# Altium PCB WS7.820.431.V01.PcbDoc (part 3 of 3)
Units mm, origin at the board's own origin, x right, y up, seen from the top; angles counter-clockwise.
Board outline 461 x 63.5 mm, 4 copper layers (Top Layer, Mid-Layer1, Mid-Layer 2, Bottom Layer); 379 components, 227 nets, 1092 pads, 3835 vias.
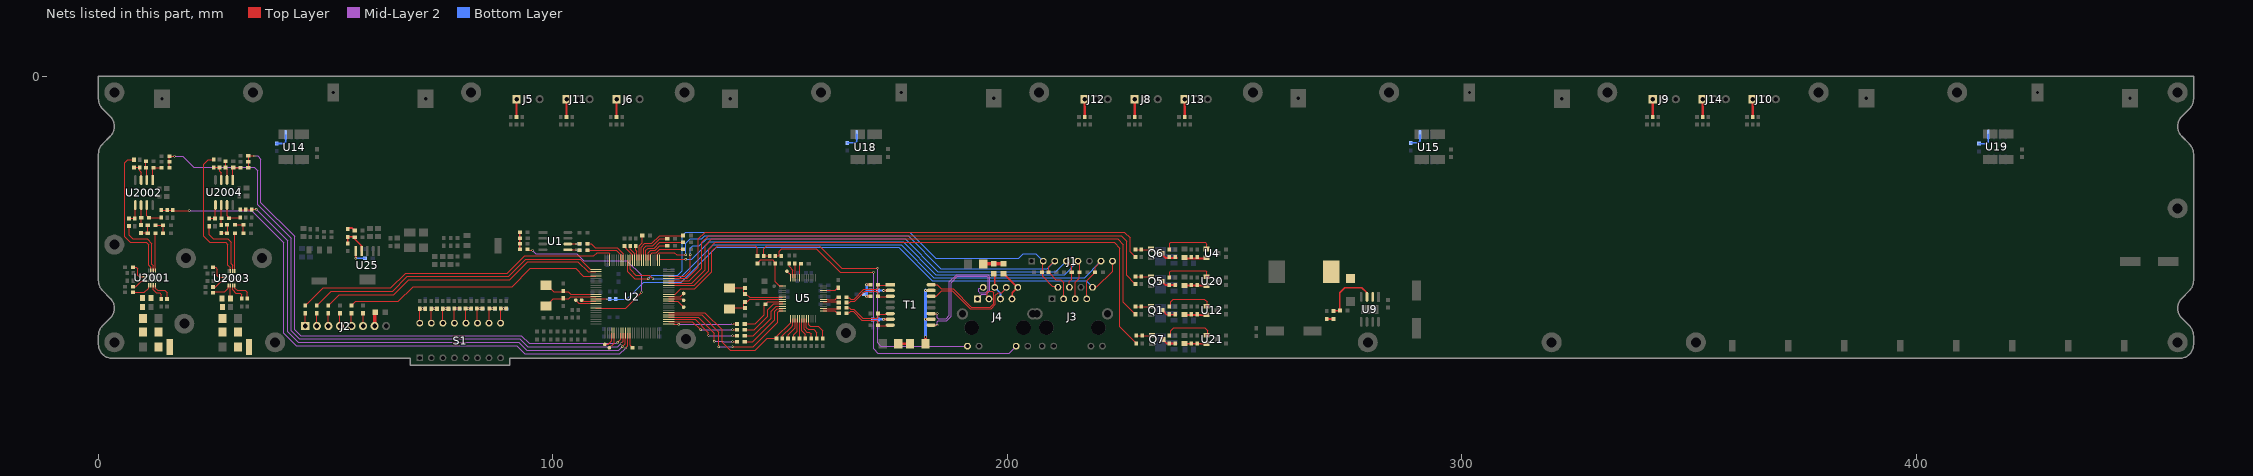
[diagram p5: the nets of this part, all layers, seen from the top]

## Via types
v1: diameter 0.508, hole 0.305, Top Layer to Bottom Layer, tented both sides, 3797 vias
v2: diameter 0.66, hole 0.406, Top Layer to Bottom Layer, tented both sides, 20 vias
v3: diameter 0.6, hole 0.305, Top Layer to Bottom Layer, tented both sides, 10 vias
v4: diameter 0.813, hole 0.508, Top Layer to Bottom Layer, tented both sides, 7 vias
v5: diameter 0.508, hole 0.3, Top Layer to Bottom Layer, tented both sides, 1 vias

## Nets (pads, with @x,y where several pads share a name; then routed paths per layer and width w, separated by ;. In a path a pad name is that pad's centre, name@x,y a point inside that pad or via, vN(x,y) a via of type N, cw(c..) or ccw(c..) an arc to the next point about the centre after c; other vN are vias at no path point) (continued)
IO11: D4.1 R91.2 R177.1 S1.16 | length 5
  Top Layer w0.254: S1.16@70.705,-54.25 R91.2@70.705,-51.105
  Top Layer w0.508: R91.2@70.705,-51.104 R177.1@71.912,-51.104
  Bottom Layer w0.508: v1(71.294,-51.104) 71.889,-51.104 D4.1@71.909,-51.125
IO12: D2.1 R27.1 R175.2 S1.15 | length 6.3
  Top Layer w0.254: S1.15@73.245,-54.25 R175.2@73.245,-51.107 ; R27.1@74.495,-51.104 v1(73.86,-51.104) R175.2@73.245,-51.104 ; R175.2@73.245,-51.107 R175.2@73.245,-51.104 ; R175.2@73.245,-51.107 R175.2@73.242,-51.104 R175.2@73.245,-51.104
  Top Layer w0.508: R175.2@73.242,-51.104 R27.1@74.495,-51.104
  Bottom Layer w0.254: v1@73.849,-51.115 v1(73.86,-51.104)
  Bottom Layer w0.508: v1(73.86,-51.104) 74.499,-51.104 D2.1@74.52,-51.125
IO13: D3.1 R25.1 R176.2 S1.14 | length 6.4
  Top Layer w0.254: S1.14@75.785,-54.25 R176.2@75.785,-51.125 ; R25.1@77.035,-51.104 v1(76.4,-51.104) R176.2@75.785,-51.104 ; R176.2@75.785,-51.125 R176.2@75.785,-51.104 ; R176.2@75.785,-51.125 R176.2@75.765,-51.104 R176.2@75.785,-51.104
  Top Layer w0.508: R176.2@75.765,-51.104 R25.1@77.035,-51.104
  Bottom Layer w0.508: v1(76.4,-51.104) 77.039,-51.104 D3.1@77.06,-51.125
IO14: D6.1 R118.1 R119.2 S1.13 | length 5.1
  Top Layer w0.254: S1.13@78.325,-54.25 R119.2@78.325,-51.175 ; R119.2@78.325,-51.175 78.325,-51.1 R119.2@78.25,-51.1 R119.2@78.325,-51.175
  Top Layer w0.508: R119.2@78.325,-51.1 v1(78.885,-51.1) R118.1@79.5,-51.1
  Bottom Layer w0.508: v1(78.885,-51.1) 79.436,-51.1 D6.1@79.461,-51.125
IO15: D5.1 R120.1 R121.2 S1.12 | length 5
  Top Layer w0.254: S1.12@80.81,-54.25 R121.2@80.81,-51.16
  Top Layer w0.508: R121.2@80.75,-51.1 v1(81.385,-51.1) R120.1@82,-51.1
  Bottom Layer w0.508: v1(81.385,-51.1) 81.976,-51.1 D5.1@82.001,-51.125
IO16: D8.1 R132.1 R133.2 S1.11 | length 5.2
  Top Layer w0.254: R133.2@83.25,-51.1 R133.2@83.31,-51.16 ; S1.11@83.31,-54.25 R133.2@83.31,-51.16 ; R133.2@83.396,-51.246 R133.2@83.31,-51.16
  Top Layer w0.508: R133.2@83.25,-51.1 v1(83.885,-51.1) R132.1@84.5,-51.1
  Bottom Layer w0.508: v1(83.885,-51.1) 84.45,-51.1 D8.1@84.5,-51.15
IO17: D9.1 R9.1 R13.2 S1.10 | length 5.1
  Top Layer w0.254: S1.10@85.945,-54.25 R13.2@85.945,-51.155 ; R13.2@85.945,-51.1 R13.2@85.945,-51.155 ; R13.2@86,-51.1 R13.2@85.945,-51.155
  Top Layer w0.508: R13.2@86,-51.1 R9.1@87.25,-51.1
  Bottom Layer w0.508: v1(86.625,-51.1) 87.2,-51.1 D9.1@87.25,-51.15
IO18: D7.1 R14.1 R61.2 S1.9 | length 5.1
  Top Layer w0.254: S1.9@88.485,-54.25 R61.2@88.485,-51.115 ; R61.2@88.485,-51.1 R61.2@88.485,-51.115 ; R61.2@88.5,-51.1 R61.2@88.485,-51.115
  Top Layer w0.508: R61.2@88.5,-51.1 R14.1@89.75,-51.1
  Bottom Layer w0.508: v1(89.125,-51.1) 89.7,-51.1 D7.1@89.75,-51.15
JTCK: J1.5 J3.5 R8.2 U2.76 | length 107.2
  Top Layer w0.254: U2.76@123.468,-40.455 123.468,-40.267 123.485,-40.25 v1(129.25,-40.25) ; J3.5@214.92,-48.929 214.92,-45.33 215.834,-44.416 215.834,-43.163 R8.2@215.884,-43.113 215.884,-40.897 J1.5@215.383,-40.396
  Bottom Layer w0.254: v1(129.25,-40.25) 130.5,-40.25 134.396,-36.354 177.044,-36.354 184.271,-43.581 212.579,-43.581 J1.5@215.51,-40.65
JTDI: J1.3 J3.3 R5.1 U2.77 | length 106.8
  Top Layer w0.254: U2.77@122.968,-40.455 122.968,-39.228 123.446,-38.75 126.75,-38.75 127.25,-39.25 v1(129.25,-39.25) ; J1.3@210.303,-40.65 209.057,-41.896 R5.1@209.057,-43.113 209.107,-43.113 209.38,-43.386 209.38,-43.436 210.693,-44.75 211.693,-44.75 212.38,-45.437 J3.3@212.38,-48.929
  Bottom Layer w0.254: v1(129.25,-39.25) 129.25,-36.75 130.25,-35.75 132.75,-35.75 133.46,-35.04 178.139,-35.04 185.366,-42.267 208.813,-42.267 J1.3@210.43,-40.65
JTDO: J1.7 J3.7 R7.1 U2.89 | length 123.7
  Top Layer w0.254: U2.89@116.968,-40.455 116.968,-42.468 118.25,-43.75 121.25,-43.75 v1(122,-44.5) ; J3.7@217.46,-48.929 217.46,-44.951 218.975,-43.436 218.975,-43.386 219.248,-43.113 R7.1@219.298,-43.113 219.298,-41.942 J1.7@220.59,-40.65
  Bottom Layer w0.254: v1(122,-44.5) 127.75,-44.5 135.239,-37.011 176.606,-37.011 183.845,-44.25 216.99,-44.25 J1.7@220.59,-40.65
JTMS: J1.4 J3.4 R6.1 U2.72 | length 104.5
  Top Layer w0.254: U2.72@125.468,-43.955 129.045,-43.955 130.25,-42.75 v1(130.25,-39.25) ; J1.4@212.843,-40.396 214.171,-41.723 R6.1@214.171,-43.113 214.171,-44.579 213.65,-45.1 J3.4@213.65,-46.389
  Bottom Layer w0.254: v1(130.25,-39.25) 130.25,-37.75 130.75,-37.25 132.25,-37.25 133.803,-35.697 177.482,-35.697 184.709,-42.924 210.696,-42.924 J1.4@212.97,-40.65
LINKLED: R50.2 R77.2 U5.25 | length 10.7
  Top Layer w0.254: R77.2@145,-41.164 145,-41.114 145.73,-40.384 148.325,-40.384 148.686,-40.745 148.686,-40.891 R50.2@148.959,-41.164 148.959,-45.21 149.815,-46.066 U5.25@150.529,-46.066
M_SCL: R2.1 R12.2 U1.6 | length 3.3
  Top Layer w0.254: U1.6@103.285,-36.865 v1(105.082,-36.865) R12.2@105.857,-36.865
  Bottom Layer w0.254: v1(105.082,-36.865) R2.1@105.857,-36.865
M_SDA: R3.1 R11.2 U1.5 | length 3.3
  Top Layer w0.254: U1.5@103.285,-38.135 v1(105.082,-38.135) 105.798,-38.135 R11.2@105.878,-38.215
  Bottom Layer w0.254: v1(105.082,-38.135) R3.1@105.798,-38.135
NetC10_1: C10.1 U2.12 X1.2 | length 12
  Top Layer w0.254: X1.2@98.465,-45.814 X1.2@98.618,-45.814 ; X1.2@98.77,-45.814 X1.2@98.618,-45.814 ; U2.12@109.468,-47.955 103.959,-47.955 103.375,-47.37 100.174,-47.37 X1.2@98.618,-45.814
NetC11_1: C11.1 U2.13 X1.1 | length 11.9
  Top Layer w0.254: X1.1@98.465,-50.537 100.063,-48.938 103.468,-48.938 103.951,-48.455 U2.13@109.468,-48.455
NetC15_2: C15.2 C19.1 FB15.1 U12.2 | length 4.8
  Top Layer w0.508: FB15.1@239.195,-52.475 239.22,-52.5 243.962,-52.5 U12.2@243.987,-52.525
NetC18_1: C18.1 C141.2 FB18.1 U4.2 | length 5
  Top Layer w0.381: FB18.1@238.888,-40.007 238.938,-40.057 240.539,-40.057 U4.2@243.911,-40.057
NetC33_2: C33.2 R33.1 R35.1 R37.1 | length 5
  Top Layer w0.508: v3(169.024,-48.359) R35.1@169.85,-48.359 ; v3(169.024,-45.819) R37.1@169.85,-45.819
  Bottom Layer w0.508: v3(169.024,-48.359) 169.024,-47.089 ; v3(169.024,-45.819) 169.024,-47.089 ; R33.1@169.85,-47.089 169.024,-47.089
NetC35_2: C35.2 R47.2 U5.30 X2.2 | length 13.2
  Top Layer w0.254: X2.2@138.849,-46.567 138.874,-46.542 142.024,-46.542 142.024,-47.89 R47.2@142.151,-48.017 ; R47.2@142.278,-47.89 142.589,-47.89 143.265,-48.566 U5.30@150.529,-48.566
NetC36_2: C36.2 J4.9 R45.1 | length 66.7
  Top Layer w0.254: R45.1@147.689,-39.464 C36.2@146.419,-39.464 146.419,-37.901 147.09,-37.23 158.575,-37.23 163.564,-42.219 v1(171.438,-42.219)
  Mid-Layer 2 w0.254: v1(171.438,-42.219) 171.438,-58.602 172.189,-59.353 J4.9@191.22,-59.353
NetC37_2: C37.2 R47.1 U5.31 X2.1 | length 13.3
  Top Layer w0.254: X2.1@138.849,-51.167 139.078,-50.938 142.024,-50.938 142.024,-49.59 R47.1@142.151,-49.463 ; R47.1@142.278,-49.59 142.765,-49.59 143.289,-49.066 U5.31@150.529,-49.066
NetC38_2: C38.2 U5.20 | length 3.3
  Top Layer w0.254: U5.20@154.279,-44.316 154.279,-41.399 C38.2@154.521,-41.157
NetC39_2: C39.2 J4.11 R50.1 | length 74.5
  Top Layer w0.254: R50.1@148.679,-39.457 149.822,-39.457 149.822,-38.435 150.37,-37.887 157.962,-37.887 163.183,-43.108 v1(170.549,-43.108)
  Mid-Layer 2 w0.254: v1(170.549,-43.108) 170.549,-59.954 171.477,-60.882 200.411,-60.882 J4.11@201.94,-59.353
NetC40_2: C40.2 U5.22 | length 3.2
  Top Layer w0.254: U5.22@153.279,-44.316 C40.2@153.279,-41.158
NetC41_2: C41.2 R46.1 R48.1 | length 4.7
  Top Layer w0.762: C41.2@194.45,-41.25 194.475,-41.225 196.975,-41.225 R46.1@197,-41.2 R48.1@199.125,-41.2
NetC42_2: C42.2 R51.1 | length 2.6
  Top Layer w0.508: C42.2@175.985,-58.809 R51.1@178.554,-58.809
NetC61_2: C61.2 C75.1 FB16.1 U20.2 | length 5
  Top Layer w0.381: FB16.1@238.888,-45.959 238.938,-46.009 239.818,-46.009 240.539,-46.009 U20.2@243.911,-46.009
NetC74_2: C74.2 C91.1 FB17.1 U21.2 | length 4.5
  Top Layer w0.381: FB17.1@238.945,-58.8 241.739,-58.8 U21.2@243.41,-58.8 ; U21.2@244.067,-58.8 U21.2@244.117,-58.85
NetC82_2: C82.2 R83.2 R84.2 R86.2 | length 3.9
  Top Layer w0.381: R84.2@92.725,-38.059 C82.2@92.725,-36.789 92.725,-34.21 R83.2@92.763,-34.173
NetC184_1: C184.1 R168.1 R169.1 U25.4 | length 6.7
  Top Layer w0.381: R169.1@54.835,-36.738 R168.1@54.835,-35.293 56.325,-35.293 C184.1@56.398,-35.366 56.398,-35.773 57.887,-37.262 U25.4@57.887,-38.455
NetC2003_1: C2003.1 U2001.14 | length 4.4
  Top Layer w0.254: C2003.1@7.561,-41.953 8.311,-41.953 8.667,-42.308 8.667,-43.756 9.001,-44.09 U2001.14@10.19,-44.09
NetC2004_1: C2004.1 U2001.16 | length 3.1
  Top Layer w0.254: C2004.1@7.561,-46.271 8.26,-46.271 9.441,-45.09 U2001.16@10.19,-45.09
NetC2007_2: C2007.2 U2001.1 | length 4.5
  Top Layer w0.254: C2007.2@7.561,-47.515 10.089,-47.515 11.04,-46.564 U2001.1@11.04,-45.94
NetC2008_1: C2008.1 R2004.1 R2010.2 R2011.2
NetC2008_2: C2008.2 U2001.2 | length 0
  Top Layer w0.254: C2008.2@11.537,-48.774 C2008.2@11.54,-48.771
NetC2009_2: C2009.2 R2003.2 U2002.3 | length 4.2
  Top Layer w0.254: R2003.2@7.816,-20.025 C2009.2@9.06,-20.025 ; C2009.2@9.052,-20.033 C2009.2@9.06,-20.025 ; U2002.3@9.382,-22.804 9.382,-21.046 9.06,-20.724 C2009.2@9.06,-20.025
NetC2010_2: C2010.2 U2001.3 | length 4.1
  Top Layer w0.254: U2001.3@12.04,-45.94 12.04,-46.927 12.731,-47.617 13.442,-47.617 13.823,-47.998 C2010.2@13.823,-48.926
NetC2017_1: C2017.1 U2003.14 | length 4.2
  Top Layer w0.254: C2017.1@25.223,-42.012 25.796,-42.012 26.151,-42.368 26.151,-43.816 26.486,-44.15 U2003.14@27.675,-44.15
NetC2018_1: C2018.1 U2003.16 | length 2.9
  Top Layer w0.254: C2018.1@25.223,-46.33 25.745,-46.33 26.925,-45.15 U2003.16@27.675,-45.15
NetC2021_2: C2021.2 U2003.1 | length 4.2
  Top Layer w0.254: C2021.2@25.262,-47.321 27.828,-47.321 28.525,-46.624 U2003.1@28.525,-46
NetC2022_1: C2022.1 R2025.1 R2032.2 R2033.2
NetC2022_2: C2022.2 U2003.2 | length 2.8
  Top Layer w0.254: C2022.2@29.022,-48.834 29.025,-48.831 U2003.2@29.025,-46
NetC2025_2: C2025.2 R2026.2 U2004.3 | length 4.4
  Top Layer w0.254: R2026.2@25.376,-19.998 C2025.2@26.646,-19.998 ; C2025.2@26.591,-19.943 C2025.2@26.646,-19.998 ; C2025.2@26.74,-20.091 C2025.2@26.672,-20.023 ; U2004.3@27.019,-22.777 27.019,-21.197 26.672,-20.85 C2025.2@26.672,-20.023 ; C2025.2@26.646,-19.998 C2025.2@26.672,-20.023
NetC2026_2: C2026.2 U2003.3 | length 4.3
  Top Layer w0.254: U2003.3@29.525,-46 29.525,-46.986 30.215,-47.677 31.177,-47.677 31.5,-48 C2026.2@31.5,-48.9
NetD1_2: D1.2 L4.1 U9.2
NetFB2_2: FB2.2 J5.1 | length 3.9
  Top Layer w0.508: FB2.2@92,-8.9 J5.1@92,-5
NetFB3_2: FB3.2 J11.1 | length 3.9
  Top Layer w0.508: FB3.2@103,-8.9 J11.1@103,-5
NetFB4_2: FB4.2 J6.1 | length 3.9
  Top Layer w0.508: FB4.2@114,-8.9 J6.1@114,-5
NetFB5_2: FB5.2 J12.1 | length 3.9
  Top Layer w0.508: FB5.2@217,-8.9 J12.1@217,-5
NetFB6_2: FB6.2 J8.1 | length 3.9
  Top Layer w0.508: FB6.2@228,-8.9 J8.1@228,-5
NetFB9_2: FB9.2 J13.1 | length 3.9
  Top Layer w0.508: FB9.2@239,-8.9 J13.1@239,-5
NetFB10_2: FB10.2 J9.1 | length 3.9
  Top Layer w0.508: FB10.2@342,-8.9 J9.1@342,-5
NetFB11_2: FB11.2 J14.1 | length 3.9
  Top Layer w0.508: FB11.2@353,-8.9 J14.1@353,-5
NetFB12_2: FB12.2 J10.1 | length 3.9
  Top Layer w0.508: FB12.2@364,-8.9 J10.1@364,-5
NetJ2_1: J2.1 R26.1 | length 2.8
  Top Layer w0.254: J2.1@45.516,-54.912 R26.1@45.516,-52.104
NetJ2_2: J2.2 R28.1 | length 2.8
  Top Layer w0.254: J2.2@48.056,-54.912 R28.1@48.056,-52.143
NetJ2_3: J2.3 R29.1 | length 2.8
  Top Layer w0.254: J2.3@50.596,-54.912 R29.1@50.596,-52.104
NetJ2_4: J2.4 R30.1 | length 2.8
  Top Layer w0.254: J2.4@53.136,-54.912 R30.1@53.136,-52.118
NetJ2_5: J2.5 R31.1 | length 2.7
  Top Layer w0.254: J2.5@55.676,-54.912 R31.1@55.676,-52.194
NetJ2_6: J2.6 R32.1 | length 2.8
  Top Layer w0.254: J2.6@58.216,-54.912 R32.1@58.216,-52.104
NetJ2_7: J2.7 L2.1 | length 2.9
  Top Layer w0.762: J2.7@60.756,-54.912 L2.1@60.756,-52.042
NetJ4_4: J4.4 J4.5 R46.2 | length 6.4
  Top Layer w0.381: R46.2@197,-43.2 197.215,-43.415 J4.4@197.215,-46.403
  Bottom Layer w0.381: J4.4@197.215,-46.403 198.485,-47.673 J4.5@198.485,-48.943
NetJ4_7: J4.7 J4.8 R48.2 | length 7.5
  Top Layer w0.381: R48.2@199.125,-43.4 199.175,-43.4 202.178,-46.403 J4.8@202.295,-46.403 201.076,-47.621 201.076,-48.891 J4.7@201.025,-48.943
NetQ1_1: Q1.1 R95.2 R103.2 | length 3.3
  Top Layer w0.254: R95.2@228.295,-50.725 Q1.1@231.44,-50.725 ; Q1.1@231.659,-50.725 Q1.1@231.759,-50.625
NetQ1_3: Q1.3 R85.1 R88.1 | length 3.5
  Top Layer w0.381: Q1.3@234.159,-51.575 234.309,-51.575 234.618,-51.884 234.618,-52.034 235.009,-52.425 235.936,-52.425 R85.1@237.21,-52.425
NetQ5_1: Q5.1 R160.2 R162.2 | length 3.5
  Top Layer w0.254: R160.2@228.176,-43.998 228.287,-44.109 Q5.1@231.592,-44.109
NetQ5_3: Q5.3 R104.1 R107.1 | length 3.6
  Top Layer w0.381: Q5.3@233.992,-45.059 234.842,-45.909 235.764,-45.909 R104.1@237.237,-45.909
NetQ6_1: Q6.1 R183.2 R184.2 | length 3.5
  Top Layer w0.254: R183.2@228.176,-38.257 228.276,-38.157 Q6.1@231.592,-38.157
NetQ6_3: Q6.3 R87.1 R181.1 | length 3.6
  Top Layer w0.508: Q6.3@233.992,-39.107 234.842,-39.957 R181.1@237.237,-39.957
NetQ7_1: Q7.1 R161.2 R165.2 | length 3.3
  Top Layer w0.254: R161.2@228.395,-57.05 229.709,-57.05 Q7.1@231.534,-57.05 ; Q7.1@231.753,-57.05 Q7.1@231.853,-56.95
NetQ7_3: Q7.3 R105.1 R123.1 | length 3.3
  Top Layer w0.381: Q7.3@234.253,-57.9 235.103,-58.75 235.897,-58.75 R105.1@237.244,-58.75
NetR11_1: R11.1 U2.93 | length 9
  Top Layer w0.254: R11.1@107.578,-38.219 113.969,-38.219 114.968,-39.218 U2.93@114.968,-40.455
NetR12_1: R12.1 U2.92 | length 10.3
  Top Layer w0.254: R12.1@107.578,-36.843 108.425,-36.843 109.281,-37.699 114.199,-37.699 115.468,-38.968 U2.92@115.468,-40.455
NetR15_2: R15.2 U2.37 | length 3.5
  Top Layer w0.254: U2.37@116.968,-56.455 116.968,-59.147 R15.2@117.516,-59.694
NetR16_1: R16.1 U2.54 | length 18.3
  Top Layer w0.254: U2.54@125.468,-52.955 131.955,-52.955 135.5,-56.5 v1(135.5,-58.25) ; v1(139.501,-58.392) R16.1@140.505,-58.392
  Mid-Layer 2 w0.254: v1(135.5,-58.25) 137.389,-58.25 137.531,-58.392 v1(139.501,-58.392)
NetR17_1: R17.1 U2.53 | length 16.9
  Top Layer w0.254: U2.53@125.468,-53.455 131.315,-53.455 134.226,-56.365 134.226,-56.976 v1(134.25,-57) ; v1(139.501,-57.079) R17.1@140.505,-57.079
  Mid-Layer 2 w0.254: v1(134.25,-57) 134.29,-57.04 139.462,-57.04 v1(139.501,-57.079)
NetR18_1: R18.1 U2.52 | length 15.8
  Top Layer w0.254: U2.52@125.468,-53.955 130.705,-53.955 v1(132.5,-55.75) ; v1(139.501,-55.767) R18.1@140.505,-55.767
  Mid-Layer 2 w0.254: v1(132.5,-55.75) 132.508,-55.758 139.493,-55.758 v1(139.501,-55.767)
NetR19_1: R19.1 U2.51 | length 14
  Top Layer w0.254: U2.51@126.591,-54.472 126.65,-54.531 v1(127.677,-54.531) ; v1(139.501,-54.455) R19.1@140.505,-54.455
  Mid-Layer 2 w0.254: v1(127.677,-54.531) 127.715,-54.493 139.463,-54.493 v1(139.501,-54.455)
NetR49_1: R49.1 U5.45 | length 6.6
  Top Layer w0.254: U5.45@156.279,-53.316 156.279,-54.619 156.648,-54.988 158.357,-54.988 159.347,-55.978 R49.1@159.347,-57.618
NetR51_2: R51.2 T1.10 T1.15 | length 14.2
  Top Layer w0.508: R51.2@181.954,-58.809 R51.2@181.978,-58.785 ; v3(181.978,-53.439) T1.10@183.227,-53.439 ; v3(181.978,-47.089) T1.15@183.227,-47.089
  Top Layer w0.762: R51.2@181.978,-58.785 v2(181.978,-57.362)
  Bottom Layer w0.762: v2(181.978,-57.362) v3(181.978,-53.439) v3(181.978,-47.089)
NetR52_2: R52.2 U5.10 | length 3.4
  Top Layer w0.254: U5.10@159.529,-47.066 162.107,-47.066 R52.2@162.675,-46.498
NetR53_1: R53.1 U5.44 | length 6
  Top Layer w0.254: U5.44@155.779,-53.316 155.779,-55.256 156.146,-55.623 157.341,-55.623 158.077,-56.359 R53.1@158.077,-57.618
NetR54_1: R54.1 U5.43 | length 5.3
  Top Layer w0.254: U5.43@155.279,-53.316 155.279,-55.67 155.892,-56.284 156.452,-56.284 156.807,-56.638 R54.1@156.807,-57.618
NetR55_2: R55.2 U5.23 | length 3.5
  Top Layer w0.254: R55.2@151.981,-41.13 151.981,-41.812 152.779,-42.61 U5.23@152.779,-44.316
NetR56_2: R56.2 U5.38 | length 5.3
  Top Layer w0.254: R56.2@150.457,-57.618 150.457,-57.104 152.388,-55.173 152.515,-55.046 152.779,-54.782 U5.38@152.779,-53.316
NetR57_2: R57.2 U5.39 | length 4.9
  Top Layer w0.254: R57.2@151.727,-57.618 151.727,-56.824 153.279,-55.272 U5.39@153.279,-53.316
NetR58_2: R58.2 U5.40 | length 5
  Top Layer w0.254: R58.2@152.763,-57.384 R58.2@152.997,-57.618 152.997,-56.85 153.779,-56.068 U5.40@153.779,-53.316
NetR59_2: R59.2 U5.41 | length 4.9
  Top Layer w0.254: 154.267,-56.995 R59.2@154.267,-57.618 154.279,-57.606 U5.41@154.279,-53.316
NetR60_2: R60.2 U5.42 | length 4.6
  Top Layer w0.254: U5.42@154.779,-53.316 154.779,-56.008 155.537,-56.766 R60.2@155.537,-57.618
NetR77_1: R77.1 U2.64 | length 28.5
  Top Layer w0.254: U2.64@125.468,-47.955 126.935,-47.955 128.14,-46.75 131.25,-46.75 135,-43 135,-38.5 136.25,-37.25 140.75,-37.25 144.5,-37.25 145,-37.75 R77.1@145,-39.464
NetR80_1: R80.1 R166.2 | length 1.5
  Top Layer w0.381: R80.1@270.25,-53.35 R166.2@271.75,-53.35
NetR82_1: R82.1 R166.1 U9.3 | length 13.1
  Top Layer w0.381: R166.1@271.75,-51.65 271.825,-51.575 273.075,-51.575 R82.1@273.15,-51.5 273.15,-47.6 274.25,-46.5 278,-46.5 279.005,-47.506 279.005,-47.556 279.115,-47.666 U9.3@279.115,-48.5
NetR87_2: R87.2 U4.1 | length 11.2
  Top Layer w0.254: R87.2@235.764,-38.257 235.764,-36.736 236,-36.5 243.5,-36.5 243.911,-36.911 U4.1@243.911,-38.157
NetR88_2: R88.2 U12.1 | length 10.7
  Top Layer w0.254: R88.2@235.936,-50.725 235.936,-49.559 236.52,-48.975 243.345,-48.975 243.987,-49.617 U12.1@243.987,-50.625
NetR93_1: R93.1 U14.5 | length 3.7
  Bottom Layer w0.381: R93.1@39.191,-14.739 40.778,-14.739 41.183,-14.333 U14.5@41.183,-12.839
NetR94_1: R94.1 U15.5 | length 3.6
  Bottom Layer w0.381: R94.1@288.754,-14.612 290.366,-14.612 290.786,-14.192 U15.5@290.786,-12.839
NetR100_1: R100.1 U18.5 | length 3.8
  Bottom Layer w0.381: R100.1@164.802,-14.612 166.541,-14.612 166.834,-14.319 U18.5@166.834,-12.712
NetR101_1: R101.1 U19.5 | length 3.8
  Bottom Layer w0.381: R101.1@413.804,-14.789 415.416,-14.789 415.848,-14.357 U19.5@415.848,-12.749
NetR107_2: R107.2 U20.1 | length 10.7
  Top Layer w0.254: R107.2@235.764,-44.209 235.764,-42.968 236.018,-42.714 243.628,-42.714 243.911,-42.998 U20.1@243.911,-44.109
NetR109_1: R109.1 U2.88 | length 4.2
  Top Layer w0.254: R109.1@115.75,-37 R109.1@115.75,-37.35 116.023,-37.623 116.023,-37.773 117.468,-39.218 U2.88@117.468,-40.455
NetR110_1: R110.1 U2.87 | length 3.5
  Top Layer w0.254: R110.1@117,-37.35 117.032,-37.382 117.032,-38.032 117.968,-38.968 U2.87@117.968,-40.455
NetR111_1: R111.1 U2.86 | length 3.2
  Top Layer w0.254: R111.1@118.25,-37.35 118.25,-38.25 118.468,-38.468 U2.86@118.468,-40.455
NetR112_1: R112.1 U2.85 | length 5.5
  Top Layer w0.254: U2.85@118.968,-40.455 118.968,-37.282 119.65,-36.6 R112.1@119.65,-35.25
NetR113_1: R113.1 U2.84 | length 13.2
  Top Layer w0.254: U2.84@119.468,-40.455 119.468,-37.532 120.25,-36.75 121.75,-36.75 123.5,-35 R113.1@128.65,-35
NetR114_1: R114.1 U2.83 | length 8.7
  Top Layer w0.254: U2.83@119.968,-40.455 119.968,-37.782 120.5,-37.25 122,-37.25 123.5,-35.75 R114.1@125.15,-35.75
NetR115_1: R115.1 U2.82 | length 11.1
  Top Layer w0.254: U2.82@120.468,-40.455 120.468,-38.282 121,-37.75 122.25,-37.75 123.5,-36.5 R115.1@128.65,-36.5
NetR116_1: R116.1 U2.81 | length 6.3
  Top Layer w0.254: U2.81@120.968,-40.455 120.968,-38.782 121.5,-38.25 122.5,-38.25 123.5,-37.25 R116.1@125,-37.25
NetR117_1: R117.1 U2.80 | length 8.9
  Top Layer w0.254: U2.80@121.468,-40.455 121.468,-39.181 121.899,-38.75 122.75,-38.75 123.5,-38 R117.1@128.65,-38
NetR123_2: R123.2 U21.1 | length 10.8
  Top Layer w0.254: R123.2@235.897,-57.05 235.897,-55.999 236.596,-55.3 243.462,-55.3 244.117,-55.955 U21.1@244.117,-56.95
NetR167_1: R167.1 R168.2 | length 1.9
  Top Layer w0.381: R168.2@54.835,-33.593 54.835,-33.564 55.045,-33.355 55.848,-33.355 56.139,-33.645 56.139,-33.695 56.348,-33.905 R167.1@56.398,-33.905
NetR231_1: R231.1 U25.5 | length 3.6
  Top Layer w0.381: v1(56.613,-40.001) 56.617,-39.997 U25.5@56.617,-38.455
  Bottom Layer w0.381: v1(56.613,-40.001) 56.614,-40 R231.1@58.65,-40
NetR2002_1: R2002.1 R2006.2 U2002.5 | length 4
  Top Layer w0.254: R2006.2@6.723,-31.228 R2002.1@7.923,-31.228 ; R2002.1@8.112,-31.09 U2002.5@8.112,-28.304
NetR2007_2: R2007.2 R2017.2 U2002.7 | length 5.9
  Top Layer w0.254: U2002.7@10.652,-28.126 10.652,-30.622 R2017.2@11.121,-31.091 13.805,-31.091 R2007.2@13.853,-31.043
NetR2008_1: R2008.1 R2019.2 U2002.1 | length 4.3
  Top Layer w0.254: U2002.1@11.922,-22.804 R2019.2@11.922,-20.295 ; R2019.2@12.12,-20.098 R2008.1@13.892,-20.098
NetR2012_2: R2012.2 R2013.1 R2014.2 | length 3.3
  Top Layer w0.254: R2013.1@9.348,-34.426 10.766,-34.426 R2012.2@10.84,-34.5 R2014.2@10.84,-32.75
NetR2013_2: R2013.2 R2017.1 U2002.6 | length 4.5
  Top Layer w0.254: U2002.6@9.382,-28.126 9.382,-32.576 R2013.2@9.421,-32.615
NetR2015_2: R2015.2 U2001.4 | length 5
  Top Layer w0.254: U2001.4@12.54,-45.94 12.54,-46.563 13.01,-47.033 14.559,-47.033 15.093,-47.566 R2015.2@15.093,-48.926
NetR2018_2: R2018.2 R2019.1 U2002.2 | length 4.2
  Top Layer w0.254: R2018.2@10.42,-18.667 R2019.1@10.42,-20.098 10.652,-20.33 U2002.2@10.652,-22.804
NetR2021_2: R2021.2 R2023.2 U2004.5 | length 4.4
  Top Layer w0.254: R2023.2@24.36,-31.252 R2021.2@25.635,-31.252 25.749,-31.138 U2004.5@25.749,-28.277 U2004.5@25.749,-28.125
NetR2024_2: R2024.2 R2036.2 U2004.7 | length 5.7
  Top Layer w0.254: U2004.7@28.289,-28.125 U2004.7@28.289,-28.277 28.289,-30.621 R2036.2@28.758,-31.09 ; R2036.2@28.631,-31.09 R2036.2@28.758,-31.09 ; R2024.2@31.184,-31.016 31.111,-31.09 R2036.2@28.758,-31.09
NetR2028_2: R2028.2 R2029.1 R2034.2 | length 3.3
  Top Layer w0.254: R2029.1@26.985,-34.425 28.365,-34.425 28.438,-34.498 R2034.2@28.438,-32.652
NetR2029_2: R2029.2 R2036.1 U2004.6 | length 4.5
  Top Layer w0.254: U2004.6@27.019,-28.125 27.019,-32.575 R2029.2@27.058,-32.614
NetR2030_1: R2030.1 R2038.2 U2004.1 | length 4.4
  Top Layer w0.254: U2004.1@29.559,-22.777 29.559,-20.85 29.559,-20.133 R2038.2@29.655,-20.037 ; R2038.2@29.61,-20.049 R2030.1@31.257,-20.049
NetR2035_2: R2035.2 U2003.4 | length 5.1
  Top Layer w0.254: U2003.4@30.025,-46 30.025,-46.623 30.495,-47.092 32.342,-47.092 32.75,-47.5 R2035.2@32.75,-48.9
NetR2037_2: R2037.2 R2038.1 U2004.2 | length 4.4
  Top Layer w0.254: R2037.2@28.01,-18.694 R2037.2@27.955,-18.64 R2038.1@27.955,-20.037 28.289,-20.371 U2004.2@28.289,-22.777
NetTP9_1: TP9.1 U2.63 | length 3.6
  Top Layer w0.254: U2.63@125.468,-48.455 128.045,-48.455 TP9.1@128.75,-47.75
NetTP10_1: TP10.1 U2.61 | length 3.8
  Top Layer w0.254: U2.61@125.468,-49.455 127.455,-49.455 TP10.1@128.75,-50.75
NetTP11_1: TP11.1 U2.62 | length 3.4
  Top Layer w0.254: U2.62@125.468,-48.955 128.307,-48.955 128.602,-49.25 TP11.1@128.75,-49.25
NetTP12_1: TP12.1 U2.30 | length 3.7
  Top Layer w0.254: TP12.1@112.426,-59.714 113.468,-58.672 U2.30@113.468,-56.455
NetTP13_1: TP13.1 U2.15 | length 3.2
  Top Layer w0.254: TP13.1@106.301,-49.28 106.475,-49.455 U2.15@109.468,-49.455
NetTP14_1: TP14.1 U2.16 | length 4.7
  Top Layer w0.254: TP14.1@105.031,-49.28 105.705,-49.955 U2.16@109.468,-49.955
NetTP21_1: TP21.1 U2.29 | length 3.6
  Top Layer w0.254: TP21.1@111.426,-58.964 112.176,-58.964 112.968,-58.172 U2.29@112.968,-56.455
NJTRST: J1.2 J3.2 R4.1 U2.90 | length 114.7
  Top Layer w0.254: U2.90@116.468,-40.455 116.468,-42.968 118,-44.5 v1(121,-44.5) ; J1.2@207.763,-40.65 207.763,-42.947 R4.1@207.597,-43.113 207.75,-43.266 207.75,-44 209.901,-46.151 210.872,-46.151 J3.2@211.11,-46.389
  Bottom Layer w0.254: v1(121,-44.5) 121.75,-43.75 127.5,-43.75 128.5,-42.75 128.5,-35 129.25,-34.25 178.5,-34.25 184.25,-40 202.5,-40 203.5,-39 206.241,-39 J1.2@207.89,-40.65
NRST_CPU: C2.2 J1.8 J3.8 R1.1 U2.14 | length 125.7
  Top Layer w0.254: U2.14@109.468,-48.955 v1(111.889,-48.955) ; J3.8@218.73,-46.389 218.832,-46.288 219.712,-46.288 223.13,-42.87 J1.8@223.13,-40.65
  Bottom Layer w0.254: v1(111.889,-48.955) 112.11,-48.955 112.143,-48.987 R1.1@112.524,-48.987 C2.2@113.794,-48.987 116.263,-48.987 120,-45.25 128.25,-45.25 135.935,-37.565 176.065,-37.565 183.5,-45 217.341,-45 J3.8@218.73,-46.389
OPD1: R2004.2 R2009.2 SMA2001.1
OPD_REF: R2012.1 U2001.9 | length 8.2
  Top Layer w0.254: U2001.9@12.54,-42.74 R2012.1@12.54,-34.5
OPD_VENV: R2006.1 U2001.10 | length 13.9
  Top Layer w0.254: R2006.1@6.723,-32.928 6.723,-34.973 7.5,-35.75 10.75,-35.75 11.778,-36.778 11.778,-41.332 12.04,-41.594 U2001.10@12.04,-42.74
OPD_VRMS: R2003.1 U2001.11 | length 30.5
  Top Layer w0.254: R2003.1@7.816,-18.325 6.425,-18.325 5.75,-19 5.75,-35.25 7,-36.5 10.5,-36.5 11.037,-37.037 11.037,-41.505 11.54,-42.009 U2001.11@11.54,-42.74
OUT1_REF: R2005.1 R2014.1 R2016.2 | length 3.5
  Top Layer w0.254: R2014.1@12.54,-32.75 R2016.2@14.24,-32.75 R2005.1@14.24,-34.5
OUT2_REF: R2020.1 R2027.2 R2034.1 | length 3.7
  Top Layer w0.254: R2034.1@30.011,-32.652 R2027.2@31.9,-32.652 R2020.1@31.9,-34.5
POWER_LED: R26.2 U2.98 | length 73.4
  Top Layer w0.254: R26.2@45.516,-50.404 45.516,-50.354 45.789,-50.081 45.839,-50.081 49.42,-46.5 64.35,-46.5 67.6,-43.25 90,-43.25 93.75,-39.5 109,-39.5 109.75,-38.75 112.25,-38.75 112.468,-38.968 U2.98@112.468,-40.455
PTT_SW1: R183.1 U2.71 | length 114.7
  Top Layer w0.254: U2.71@125.468,-44.455 129.545,-44.455 132,-42 132,-35.75 133.5,-34.25 225.75,-34.25 227,-35.5 227,-38.543 228.175,-39.718 R183.1@228.175,-39.768
PTT_SW2: R160.1 U2.70 | length 119
  Top Layer w0.254: U2.70@125.468,-44.955 130.045,-44.955 132.75,-42.25 132.75,-36.5 134.25,-35 140,-35 225,-35 226.25,-36.25 226.25,-43.756 227.852,-45.358 227.902,-45.358 228.175,-45.631 R160.1@228.175,-45.681
PTT_SW3: R95.1 U2.69 | length 124.1
  Top Layer w0.254: U2.69@125.468,-45.455 130.545,-45.455 133.5,-42.5 133.5,-37.25 135,-35.75 224.25,-35.75 225.5,-37 225.5,-49.64 227.852,-51.992 227.902,-51.992 228.175,-52.265 R95.1@228.175,-52.315
PTT_SW4: R161.1 U2.68 | length 129
  Top Layer w0.254: U2.68@125.468,-45.955 131.045,-45.955 134.25,-42.75 134.25,-38 135.75,-36.5 223.5,-36.5 224.75,-37.75 224.75,-55.084 228.071,-58.405 228.121,-58.405 228.394,-58.678 R161.1@228.394,-58.728
RFOUT_LED: R28.2 U2.1 | length 66.5
  Top Layer w0.254: R28.2@48.056,-50.354 48.329,-50.081 48.379,-50.081 51.21,-47.25 64.75,-47.25 68,-44 90.25,-44 94,-40.25 105.989,-40.25 108.194,-42.455 U2.1@109.468,-42.455
RPD1: R2025.2 R2031.2 SMA2002.1
RPD_EREF: R2028.1 U2003.9 | length 8.3
  Top Layer w0.254: R2028.1@30.011,-34.498 30.025,-34.512 U2003.9@30.025,-42.8
RPD_VENV: R2023.1 U2003.10 | length 13.9
  Top Layer w0.254: R2023.1@24.36,-32.952 24.36,-34.86 25.25,-35.75 28.5,-35.75 29.25,-36.5 29.25,-41.25 29.525,-41.525 U2003.10@29.525,-42.8
RPD_VRMS: R2026.1 U2003.11 | length 30.6
  Top Layer w0.254: R2026.1@25.376,-18.298 24.207,-18.298 23.155,-19.35 23.155,-35.155 24.5,-36.5 28,-36.5 28.5,-37 28.5,-41.5 29.025,-42.025 U2003.11@29.025,-42.8
RTC: R33.2 T1.2 | length 2.7
  Top Layer w0.508: v3(172.758,-47.089) T1.2@174.227,-47.089
  Bottom Layer w0.508: R33.2@171.55,-47.089 v3(172.758,-47.089)
RX1_N: J4.6 T1.14 | length 21.9
  Top Layer w0.191: T1.14@183.227,-48.359 184.373,-48.359 185.56,-47.172 187.922,-47.172 191.881,-51.131 196.408,-51.131 197.381,-50.158 197.381,-48.159 197.95,-47.591 198.771,-47.591 199.755,-46.606 J4.6@199.755,-46.403
RX1_P: J4.3 T1.16 | length 21.7
  Top Layer w0.191: T1.16@183.227,-45.819 184.538,-45.819 185.484,-46.766 188.054,-46.766 192.039,-50.75 196.25,-50.75 197,-50 197,-47.64 196.677,-47.317 195.793,-47.317 195.574,-47.536 195.574,-48.572 J4.3@195.945,-48.943
RX_N: R42.1 U5.5 | length 3.8
  Top Layer w0.191: U5.5@159.529,-49.566 160.43,-49.566 160.477,-49.519 R42.1@162.663,-49.519 ; R42.1@162.663,-49.519 R42.1@162.891,-49.748 R42.1@162.663,-49.519
RX_P: R40.1 U5.6 | length 3.6
  Top Layer w0.191: U5.6@159.529,-49.066 160.43,-49.066 160.477,-49.113 162.079,-49.113 162.503,-48.689 R40.1@162.891,-48.689
SPDLED: TP2.1 U5.24 | length 1.8
  Top Layer w0.254: TP2.1@151.499,-42.854 152.279,-43.634 U5.24@152.279,-44.316
SPI2_MISO: R17.2 U5.34 | length 11.9
  Top Layer w0.254: R17.2@142.205,-57.079 144.116,-57.079 148.018,-53.177 148.018,-51.712 149.164,-50.566 U5.34@150.529,-50.566
SPI2_MOSI: R16.2 U5.35 | length 12.5
  Top Layer w0.254: R16.2@142.205,-58.392 143.972,-58.392 148.806,-53.558 148.806,-51.661 149.4,-51.066 U5.35@150.529,-51.066
SPI2_NSS: R19.2 R41.1 U5.32 | length 11.6
  Top Layer w0.254: R19.2@142.205,-54.455 144.505,-54.455 146.5,-52.46 146.5,-50.321 147.255,-49.566 U5.32@150.529,-49.566
SPI2_SCK: R18.2 U5.33 | length 11.5
  Top Layer w0.254: R18.2@142.205,-55.767 144.285,-55.767 147.307,-52.745 147.307,-51.331 148.572,-50.066 U5.33@150.529,-50.066
TCT: C34.2 R38.1 T1.7 | length 3.8
  Top Layer w0.508: v3(172.758,-53.439) T1.7@174.227,-53.439
  Bottom Layer w0.508: R38.1@170.446,-53.351 170.459,-53.364 170.534,-53.439 171.55,-53.439 v3(172.758,-53.439)
TEMP_LED: R31.2 U2.4 | length 57.9
  Top Layer w0.254: R31.2@55.676,-50.404 55.676,-50.354 55.949,-50.081 55.999,-50.081 56.58,-49.5 66,-49.5 69.25,-46.25 91,-46.25 95,-42.25 104.986,-42.25 106.69,-43.955 U2.4@109.468,-43.955
TX1_N: J4.2 T1.9 | length 28.7
  Top Layer w0.191: T1.9@183.227,-54.709 v1(184.538,-54.709)
  Mid-Layer 2 w0.191: v1(184.538,-54.709) 184.538,-53.986 184.824,-53.7 186.683,-53.7 187.631,-52.752 187.631,-45.369 189,-44 195.5,-44 195.75,-44.25 195.75,-47.03 195.234,-47.546 193.862,-47.546 193.71,-47.394 193.71,-46.745 193.821,-46.633 194.445,-46.633 J4.2@194.675,-46.403
TX1_P: J4.1 T1.11 | length 29
  Top Layer w0.191: T1.11@183.227,-52.169 v1(184.538,-52.169)
  Mid-Layer 2 w0.191: v1(184.538,-52.169) 184.538,-53.058 184.773,-53.293 186.551,-53.293 187.25,-52.594 187.25,-45.211 188.842,-43.619 195.658,-43.619 196.174,-44.135 196.174,-47.181 195.402,-47.952 194.396,-47.952 J4.1@193.405,-48.943
TX_N: R44.1 U5.1 | length 3.6
  Top Layer w0.191: U5.1@159.529,-51.566 160.43,-51.566 160.477,-51.519 162.018,-51.519 162.489,-51.991 R44.1@162.891,-51.991
TX_P: R43.1 U5.2 | length 4.2
  Top Layer w0.191: U5.2@159.529,-51.066 160.43,-51.066 160.477,-51.113 R43.1@162.954,-51.113 ; 162.257,-51.113 162.268,-51.102 162.721,-51.102 R43.1@162.891,-50.933
VENV+: C2012.2 C2014.2 R2007.1 U2.36 | length 131
  Top Layer w0.254: R2007.1@13.819,-29.343 13.864,-29.389 C2012.2@16.37,-29.389 16.481,-29.5 v1(20,-29.5) ; v1(116,-59.75) 116.468,-59.282 U2.36@116.468,-56.455
  Mid-Layer 2 w0.254: v1(20,-29.5) 33.75,-29.5 40.8,-36.55 40.8,-56.48 43.57,-59.25 92,-59.25 93.75,-61 114.75,-61 v1(116,-59.75)
VENV-: C2023.2 C2024.2 R2024.1 U2.35 | length 112.4
  Top Layer w0.254: R2024.1@31.184,-29.316 C2023.2@32.425,-29.316 ; C2023.2@32.425,-29.302 32.473,-29.35 33.648,-29.35 C2024.2@33.695,-29.302 ; C2024.2@33.695,-29.316 33.762,-29.25 v1(34.75,-29.25) ; v1(115.25,-59.5) 115.968,-58.782 U2.35@115.968,-56.455
  Mid-Layer 2 w0.254: v1(34.75,-29.25) 41.6,-36.1 41.6,-56.16 43.94,-58.5 92.5,-58.5 94.25,-60.25 114.474,-60.25 115.224,-59.5 v1(115.25,-59.5)
VOLT_DEC: R84.1 U2.18 | length 42.6
  Top Layer w0.254: R84.1@94.425,-38.059 94.617,-38.25 v1(95.5,-38.25) ; U2.18@109.468,-50.955 116.045,-50.955 v1(119.5,-47.5)
  Mid-Layer 2 w0.254: v1(95.5,-38.25) 96.25,-39 105.25,-39 106.75,-40.5 116.25,-40.5 119.5,-43.75 v1(119.5,-47.5)
VRMS+: C2011.2 C2013.2 R2008.2 U2.34 | length 138.3
  Top Layer w0.254: R2008.2@15.592,-20.098 C2011.2@15.592,-18.794 C2013.2@15.592,-17.524 v1(16.733,-17.524) ; v1(115,-58.75) 115.468,-58.282 U2.34@115.468,-56.455
  Mid-Layer 2 w0.254: v1@16.893,-17.524 18.524,-17.524 21,-20 34.25,-20 35,-20.75 35,-28.25 42.4,-35.65 42.4,-56 44.15,-57.75 92.75,-57.75 94.5,-59.5 114.25,-59.5 v1(115,-58.75)
VRMS-: C2027.2 C2028.2 R2030.2 U2.33 | length 121
  Top Layer w0.254: R2030.2@33.03,-20.1 33.03,-20.049 33.03,-17.475 34.225,-17.475 v1(34.25,-17.5) ; v1(114.25,-58.5) 114.968,-57.782 U2.33@114.968,-56.455
  Mid-Layer 2 w0.254: v1(34.25,-17.5) 35,-17.5 35.75,-18.25 35.75,-27.75 43.2,-35.2 43.2,-55.68 44.52,-57 93,-57 94.75,-58.75 113.974,-58.75 114.224,-58.5 v1(114.25,-58.5)
VSWR_LED: R29.2 U2.2 | length 63.8
  Top Layer w0.254: R29.2@50.596,-50.404 50.596,-50.354 50.869,-50.081 50.919,-50.081 53,-48 65,-48 68.25,-44.75 90.5,-44.75 94.5,-40.75 105.518,-40.75 107.722,-42.955 U2.2@109.468,-42.955
W5500_INTN: U2.55 U5.36 | length 34.5
  Top Layer w0.254: U2.55@125.468,-52.455 132.705,-52.455 136.5,-56.25 v1(136.5,-59.5) ; v1(139.5,-59.491) 144.117,-59.491 149.517,-54.091 149.517,-51.839 149.789,-51.566 U5.36@150.529,-51.566
  Mid-Layer 2 w0.254: v1(136.5,-59.5) 136.505,-59.495 139.495,-59.495 v1(139.5,-59.491)
W5500_RSTN: R39.1 U2.56 U5.37 | length 35.4
  Top Layer w0.254: U2.56@125.468,-51.955 133.455,-51.955 137.25,-55.75 137.25,-58.5 139,-60.25 144.532,-60.25 147.164,-57.618 R39.1@149.187,-57.618 149.187,-57.231 152.279,-54.139 U5.37@152.279,-53.316
W5500_RX1_N: R35.2 R42.2 T1.3 | length 11.7
  Top Layer w0.191: R42.2@164.591,-49.748 165.154,-49.748 165.48,-49.422 166.42,-49.422 168.139,-47.702 168.575,-47.266 171.404,-47.266 171.55,-47.413 R35.2@171.55,-48.359 ; R35.2@171.55,-48.486 T1.3@174.227,-48.486
W5500_RX1_P: R37.2 R40.2 T1.1 | length 11.5
  Top Layer w0.191: R40.2@164.591,-48.689 165.154,-48.689 165.48,-49.015 166.251,-49.015 168.407,-46.86 171.378,-46.86 171.55,-46.688 171.55,-45.946 T1.1@174.227,-45.946
W5500_TX1_N: R34.1 R44.2 T1.8 | length 11.5
  Top Layer w0.191: R44.2@164.591,-51.991 165.154,-51.991 165.48,-51.665 166.078,-51.665 168.004,-53.591 171.259,-53.591 171.55,-53.883 R34.1@171.55,-54.709 ; R34.1@171.55,-54.836 T1.8@174.227,-54.836
W5500_TX1_P: R36.1 R43.2 T1.6 | length 11.4
  Top Layer w0.191: R43.2@164.591,-50.933 165.154,-50.933 165.48,-51.259 166.246,-51.259 168.172,-53.185 171.437,-53.185 171.55,-53.072 171.55,-52.296 T1.6@174.227,-52.296
pads on no net: J3.9 J3.10 J3.11 J3.12 J3.15 J3.16 J4.15 J4.16 T1.4 T1.5 T1.12 T1.13 U2.7 U2.8 U2.9 U2.17 U2.31 U2.32 U2.38 U2.47 U2.48 U2.57 U2.58 U2.59 U2.60 U2.65 U2.66 U2.67 U2.73 U2.78 U2.79 U2.91 U2.95 U2.96 U2.97 U5.7 U5.12 U5.13 U5.18 U5.46 U5.47 U10.4 U11.4 U14.3 U14.6 U14.7 U15.3 U15.6 U15.7 U18.3 U18.6 U18.7 U19.3 U19.6 U19.7 U2001.6 U2001.7 U2001.8 U2001.12 U2001.13 U2003.6 U2003.7 U2003.8 U2003.12 U2003.13

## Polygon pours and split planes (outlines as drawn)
GND on Mid-Layer1 "Top Layer-No Net" (solid, remove dead copper, pour order 1000): 0,-63.5 0,0 461,0 461,-63.5
GND on Top Layer "Top Layer-No Net" (solid, remove dead copper, pour order 1003): 0,0 461,0 461,-63.5 0,-63.5
GND on Bottom Layer "Top Layer-No Net" (solid, remove dead copper, pour order 1002): 0,-63.5 0,0 461,0 461,-63.5
GND on Mid-Layer 2 "Top Layer-No Net" (solid, remove dead copper, pour order 1001): 0,-63.5 0,0 461,0 461,-63.5

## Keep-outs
Keep-Out Layer:
  lines w0.254: 0,-4.96 ccw(c3.066,-4.96) 0.898,-7.128 2.602,-8.832 cw(c0.434,-11) 3.5,-11 cw(c0.434,-11) 2.602,-13.168 0.898,-14.872 ccw(c3.066,-17.04) 0,-17.04 0,-44.96 ccw(c3.066,-44.96) 0.898,-47.128 2.602,-48.832 cw(c0.434,-51) 3.5,-51 cw(c0.434,-51) 2.602,-53.168 0.898,-54.872 ccw(c3.066,-57.04) 0,-57.04 0,-59 ccw(c3,-59) 3,-62 68.655,-62 68.655,-63.5 90.535,-63.5 90.535,-62 458,-62 ccw(c458,-59) 461,-59 461,-57.04 ccw(c457.934,-57.04) 460.102,-54.872 458.398,-53.168 cw(c460.566,-51) 457.5,-51 cw(c460.566,-51) 458.398,-48.832 460.102,-47.128 ccw(c457.934,-44.96) 461,-44.96 461,-17.04 ccw(c457.934,-17.04) 460.102,-14.872 458.398,-13.168 cw(c460.566,-11) 457.5,-11 cw(c460.566,-11) 458.398,-8.832 460.102,-7.128 ccw(c457.934,-4.96) 461,-4.96 461,0 ; 0,-4.96 0,0 461,0 ; 0,-4.96 0,-4.96 ; 461,0 461,0

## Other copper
Top Layer:
  rectangle net GND: 280.45,-54.5 285,-50.25
  region net GND: 98.201,-38.301 98.201,-33.729 96.189,-33.729 96.189,-38.301
  region net NetC2022_1: 26.75,-48.25 26.75,-56 27.75,-56 27.75,-48.25
  region net RPD1: 30.25,-56.116 30.25,-59.25 31.25,-59.25 31.25,-56.116
  region net NetC2008_1: 9.05,-48.25 9.05,-57 10.05,-57 10.05,-48.25
  region net OPD1: 12.75,-56.75 12.75,-59 13.75,-59 13.75,-56.75
  rectangle net +5V: 57.648,-35.916 61.998,-34.718
  rectangle net +5V: 59.026,-35.916 61.634,-34.773
  region net 3.3VCC1: 49.102,-38.781 49.102,-34.869 48.086,-34.869 48.086,-38.781
  region net +5V: 46.943,-38.705 46.943,-34.794 44.657,-34.794 44.657,-38.705
  rectangle net 3.3VCC1: 47.82,-35.937 50.027,-34.837
  rectangle net 3.3VCC1: 49.17,-35.937 50.027,-32.864
  region net 28VOUT4: 449.25,-13.635 449.25,-8.477 386.75,-8.477 386.75,-13.635
  region net 28VOUT3: 324.25,-13.762 324.25,-8.604 261.75,-8.604 261.75,-13.762
  region net 28VOUT2: 199.273,-13.762 199.273,-8.604 136.727,-8.604 136.727,-13.762
  region net 28VOUT1: 74.273,-13.762 74.273,-8.604 11.727,-8.604 11.727,-13.762
  rectangle net 28VOUT4: 444.727,-10.89 449.273,-2.686
  rectangle net 28VOUT3: 319.727,-11.017 324.273,-2.813
  rectangle net 28VOUT2: 194.727,-11.144 199.273,-2.94
  rectangle net 28VOUT1: 11.727,-11.144 16.273,-2.94
  region net OPD1: 15.5,-59 13.75,-59 13.75,-60 15.5,-60
  region net RPD1: 33.634,-59 30.5,-59 30.5,-60 33.634,-60
  rectangle net 28VIN: 39.5,-28.289 426.75,-17.291
  rectangle net 28VOUT4: 386.727,-10.89 391.273,-2.686
  rectangle net 28VOUT3: 261.727,-11.017 266.273,-2.813
  rectangle net 28VOUT2: 136.727,-11.144 141.273,-2.94
  rectangle net +6.9V: 256.75,-58.5 261.25,-40.5
  rectangle net 28VIN: 357,-60.5 449.25,-17.25
  rectangle net 28VOUT1: 69.727,-11.144 74.273,-2.94
  rectangle net GND: 94.109,-37.175 98.681,-35.163
  rectangle net GND: 157.722,-54.325 159.119,-52.506
  region net +6.9V: 261.25,-58.75 250.5,-58.75 250,-58.25 250,-57.5 250.46,-57.04 261.25,-57.04
  pour cut-out: 258.832,-36.549 271.832,-36.549 271.832,-49.549 258.832,-49.549
  pour cut-out: 258.844,-36.586 271.844,-36.586 271.844,-49.586 258.844,-49.586
  pour cut-out: 30.431,-54.75 32.431,-54.75 32.431,-57.25 34.681,-57.25 34.681,-61 30.431,-61
  pour cut-out: 28.729,-48.888 27.482,-47.641 25.479,-47.641 25.479,-57.459 26.33,-58.31 28.729,-58.31
  pour cut-out: 13,-54.75 15,-54.75 15,-57.25 17.25,-57.25 17.25,-61 13,-61
  pour cut-out: 14.25,-48.25 14.25,-50 11.25,-50 11.25,-48.25
  pour cut-out: 10.75,-61 10.75,-51.25 11.25,-51.25 12.305,-52.305 12.305,-61
  pour cut-out: 28.381,-60.76 28.381,-52 29.805,-52 29.805,-60.76
  region net 28VIN: 284.6,-49.5 290.75,-49.5 292.5,-47.75 292.5,-26.25 286.25,-26.25 286.25,-42.25 286.25,-45.25 285,-46.5 282,-46.5 281.25,-47.25 281.25,-49.5
  region net NetD1_2: 271.75,-40.5 278.75,-40.5 280.675,-42.425 280.675,-48.825 280.5,-49 280.25,-49 280.075,-48.825 280.075,-47.325 278.25,-45.5 273,-45.5 271.75,-45.5
  pour cut-out: 424.566,0 424.566,-6.318 428.757,-6.318 428.757,0
  pour cut-out: 317.685,0.794 317.685,-13.75 326.315,-13.75 326.315,0.685 326.206,0.794
  region net +6.9VIN: 61.4,-36.75 72.5,-36.75 72.5,-38.5 64,-38.5 62.25,-40.25 61.4,-40.25
  pour cut-out: 9.685,-16.478 9.685,-13.762 252.716,-13.762 451.292,-13.762 451.292,-16.478
  pour cut-out: 442.685,0.921 442.685,-13.75 451.315,-13.75 451.315,-0.065 450.329,0.921
  pour cut-out: 384.685,0.921 384.685,-13.75 393.315,-13.75 393.315,-0.065 392.329,0.921
  pour cut-out: 192.685,0.794 192.685,-13.75 201.315,-13.75 201.315,0.435 200.956,0.794
  pour cut-out: 9.685,0.794 9.685,-13.75 18.315,-13.75 18.315,-0.636 16.885,0.794
  pour cut-out: 11.25,-48.829 10.002,-47.581 8,-47.581 8,-57.399 8.851,-58.25 11.25,-58.25
  region net NetC2008_2: 11.728,-45.5 11.372,-45.5 11.372,-47.405 11.042,-48.091 11.042,-49.219 12.042,-49.219 12.042,-48.091 11.728,-47.38
  region net NetC2022_2: 29.212,-45.56 28.856,-45.56 28.856,-47.465 28.526,-48.15 28.526,-49.279 29.526,-49.279 29.526,-48.15 29.212,-47.439
  pour cut-out: 96,-43.983 100.75,-43.983 100.75,-52.25 100.51,-52.49 96,-52.49
  pour cut-out: 110.92,-52.21 110.92,-51.194 107.872,-51.194 107.745,-51.321 107.745,-52.083 107.872,-52.21
  pour cut-out: 136.072,-44.75 140.898,-44.75 140.898,-52.246 140.47,-52.675 136.072,-52.675
  pour cut-out: 180.99,-60.003 179.466,-60.003 179.517,-59.952 179.517,-57.615 181.041,-57.615 180.99,-57.666
  pour cut-out: 175.148,-60.003 173.624,-60.003 173.675,-59.952 173.675,-57.615 175.199,-57.615 175.148,-57.666
  pour cut-out: 181.749,-49.399 181.749,-56.588 181.826,-56.664 175.603,-56.664 175.603,-43.864 181.826,-43.864 181.826,-56.664
  pour cut-out: 49.566,0 49.566,-6.318 53.757,-6.318 53.757,0
  pour cut-out: 174.566,0 174.566,-6.318 178.757,-6.318 178.757,0
  pour cut-out: 299.566,0 299.566,-6.318 303.757,-6.318 303.757,0
  pour cut-out: 259.685,0.794 259.685,-13.75 268.315,-13.75 268.315,-0.065 267.456,0.794
  pour cut-out: 134.685,0.794 134.685,-8.604 143.315,-8.604 143.315,-0.315 142.206,0.794
  pour cut-out: 67.685,0.794 67.685,-13.75 76.315,-13.75 76.315,-0.315 75.206,0.794
Mid-Layer 2:
  pour cut-out: 258.844,-36.549 271.844,-36.549 271.844,-49.549 258.844,-49.549
  pour cut-out: 181.749,-49.399 181.749,-56.588 181.826,-56.664 175.603,-56.664 175.603,-43.864 181.826,-43.864 181.826,-56.664
Mid-Layer1:
  pour cut-out: 258.832,-36.549 271.832,-36.549 271.832,-49.549 258.832,-49.549
  pour cut-out: 181.749,-49.399 181.749,-56.588 181.826,-56.664 175.603,-56.664 175.603,-43.864 181.826,-43.864 181.826,-56.664
Bottom Layer:
  rectangle net GND: 93.75,-36.75 97.25,-35.25
  region net 28VIN: 419.938,-20.223 419.938,-17.302 418.083,-17.302 418.083,-20.223
  rectangle net GND: 93,-37.151 94.333,-21.73
  rectangle net GND: 96.543,-37 98,-21.857
  region net +5V: 47.132,-38.401 47.132,-36.446 44.208,-36.446 44.208,-38.401
  region net 28VIN: 294.875,-20.313 294.875,-17.392 293.026,-17.392 293.026,-20.313
  region net 28VIN: 170.923,-20.313 170.923,-17.392 169.074,-17.392 169.074,-20.313
  region net 28VIN: 45.273,-20.313 45.273,-17.392 43.423,-17.392 43.423,-20.313
  pour cut-out: 258.844,-36.549 271.844,-36.549 271.844,-49.549 258.844,-49.549
  pour cut-out: 181.749,-49.399 181.749,-56.588 181.826,-56.664 175.603,-56.664 175.603,-43.864 181.826,-43.864 181.826,-56.664

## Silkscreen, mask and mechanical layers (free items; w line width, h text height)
Top Overlay:
  circle w0.127: c461.25,-51 r1.8
  circle w0.127: c461.25,-11 r1.8
  circle w0.127: c-0.25,-51 r1.8
  circle w0.127: c-0.25,-11 r1.8
  lines w0.254: 0,-39.513 15.972,-39.513 cw(c15.972,-42.513) 18.972,-42.513 ; 0,-37.5 38.5,-37.5 38.5,-62 ; 18.969,-42.513 18.972,-62 ; 20.972,-62 20.972,-42.5 ; 20.972,-42.513 cw(c23.972,-42.513) 23.972,-39.513 ; 24,-39.513 33.5,-39.513 cw(c33.5,-42.513) 36.5,-42.513 36.5,-62 ; -4,-66 465,-66 465,4 -4,4 -4,-66
  text "3.3V" at 205.737,-39 h1.2 r90
  text "JTRST" at 208.342,-39.062 h1.2 r90
  text "JTDI" at 210.842,-39.062 h1.2 r90
  text "JTMS" at 213.342,-39.062 h1.2 r90
  text "JTCK" at 215.842,-39.062 h1.2 r90
  text "GND" at 218.342,-39.059 h1.2 r90
  text "JTDO" at 220.842,-39.062 h1.2 r90
  text "NRST" at 223.592,-39.059 h1.2 r90
  text "WS7.820.431.V01" at 165,-40.75 h2
  text "OPD" at 5.25,-52.5 h1.52 r270
  text "RPD" at 22.5,-53 h1.52 r270
Top Solder:
  rectangle: 443.5,-60.5 449.25,-46
  region: 19.042,-38 19.042,-62 20.947,-62 20.947,-38
  region: 36.542,-37.75 36.542,-61.75 38.447,-61.75 38.447,-37.75
  region: 38.5,-37.542 0,-37.542 0,-39.447 38.5,-39.447
  rectangle: 386.75,-11.398 449.207,-8.477
  rectangle: 261.75,-11.525 324.207,-8.604
  rectangle: 136.75,-11.525 199.207,-8.604
  rectangle: 11.75,-11.525 74.207,-8.604
  rectangle: 39.5,-28.162 428,-19.526
  rectangle: 444.727,-11.373 449.273,-2.686
  rectangle: 319.727,-11.627 324.273,-2.813
  rectangle: 194.727,-8.706 199.273,-2.94
  rectangle: 11.727,-8.706 16.273,-2.94
  rectangle: 386.727,-11.373 391.273,-2.686
  rectangle: 261.727,-11.627 266.273,-2.813
  rectangle: 136.727,-8.706 141.273,-2.94
  rectangle: 69.727,-8.706 74.273,-2.94
  rectangle: 357,-60.5 443.75,-19.5
  region: 29.212,-45.56 28.856,-45.56 28.856,-47.465 28.526,-48.15 28.526,-49.279 29.526,-49.279 29.526,-48.15 29.212,-47.439
  region: 11.728,-45.5 11.372,-45.5 11.372,-47.405 11.042,-48.091 11.042,-49.219 12.042,-49.219 12.042,-48.091 11.728,-47.38
Bottom Solder:
  region: 62.75,-42.5 45.25,-42.5 45.25,-46.25 62.75,-46.25
  region: 277.334,-49.864 277.334,-52.785 282.234,-52.785 282.234,-49.864
  region: 12.705,-45.255 12.705,-43.477 10.927,-43.477 10.927,-45.255
  region: 30.189,-45.314 30.189,-43.536 28.411,-43.536 28.411,-45.314
  region: 36.5,-46.416 0,-46.416 0,-62 36.5,-62
  region: 254.457,-35.972 254.457,-62 295.664,-62 295.664,-35.972
  region: 157.371,-46.483 157.371,-51.634 166.75,-51.634 166.75,-58.634 149.5,-58.634 149.5,-49.603 152.871,-49.603 152.871,-46.483
Mechanical 1:
  lines w0.254: 357,-66 357,-63
  text "功放1 50V-1" at 17.282,8.009 h10 r90
  text "功放1 VGS" at 54.944,8.009 h10 r90
  text "功放1 50V-2" at 75.282,8.009 h10 r90
  text "功放1温度" at 97.817,8.009 h10 r90
  text "隔离器1温度" at 108.817,8.009 h10 r90
  text "功放2温度" at 119.817,8.009 h10 r90
  text "功放2 50V-1" at 142.282,8.009 h10 r90
  text "功放2 VGS" at 179.944,8.009 h10 r90
  text "功放2 50V-2" at 200.282,8.009 h10 r90
  text "隔离器2温度" at 222.817,8.009 h10 r90
  text "合成器温度" at 233.817,8.009 h10 r90
  text "功放3温度" at 244.817,8.009 h10 r90
  text "功放3 50V-1" at 267.282,8.009 h10 r90
  text "功放3 VGS" at 304.944,8.009 h10 r90
  text "功放3 50V-2" at 325.282,8.009 h10 r90
  text "隔离器3温度" at 347.817,8.009 h10 r90
  text "功放4温度" at 358.817,8.009 h10 r90
  text "隔离器4温度" at 369.817,8.009 h10 r90
  text "功放4 50V-1" at 392.282,8.009 h10 r90
  text "功放4 VGS" at 429.944,8.009 h10 r90
  text "功放4 50V-2" at 450.282,8.009 h10 r90
  text "正向检波" at 12.431,-81.009 h10 r270
  text "反向检波" at 29.863,-81.009 h10 r270
  text "灯板" at 50.814,-81.009 h10 r270
  text "地址拨码" at 76.382,-81 h10 r270
  text "LAN网口" at 194.637,-81 h10 r270
  text "JTAG" at 210.545,-81 h10 r270
  text "50V电源输入" at 414.736,-81 h10 r270
Drill Drawing:
  text "'.Legend'" at 57.5,-15.464 h1.52
Mechanical 115:
  lines w0.254: 13.6,4 14.4,4 ; 71.6,4 72.4,4 ; 138.6,4 139.4,4 ; 388.6,4 389.4,4 ; 446.6,4 447.4,4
